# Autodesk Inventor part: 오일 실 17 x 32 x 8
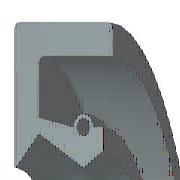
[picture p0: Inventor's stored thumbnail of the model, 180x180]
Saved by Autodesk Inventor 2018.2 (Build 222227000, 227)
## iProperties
Created: 2012-02
Part Number: 오일 실 17 x 32 x 8
Material: 고무
Description: 샤프트 실 링
Document SubType Name: Modeling
Standard: JIS B 2402
Designer: mdu-01
Standards Organization: JIS
Language: ko-KR
Size Designation: D 17 x 32 x 8
Categories: <MemberInstance><Categories><Category DisplayName="샤프트 부품" InternalName="7f7aeb1f-a693-4053-b835-cee3144e0d98" Mnemonic="SHFT"><Category DisplayName="실링" Intern
Density: 0.93 g/cm^3
Mass: 2.28027 g
Surface Area: 32.1224 cm^2
Volume: 2.45191 cm^3
Appearance: 고무 - 검은색 - 버전 1.1
IsCustomPart: 1
Author: mdu-01
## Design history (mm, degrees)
revolve "본체" stored, may be unused: angle "d17" = 90 deg
revolve "스프링1" stored, may be unused: angle "d18" = 90 deg
body "Solid1"
sketch "스케치1"
  geometry: L1 (0, 16)-(8, 16); L2 (8, 14.25)-(1.75, 14.25); L3 (1.75, 10.25)-(4.9, 8.5); L4 (4.9, 8.5)-(0, 8.5); L5 (0, 0)-(9.586, 0) reference; L6 (4.9, 8.5)-(6.3, 9.375); L7 (0, 18)-(0, -3) reference; L8 (-1.941, 0)-(11.507, 0) reference; L9 (4.2, 10.6)-(1.75, 11.21); L10 (1.75, 11.21)-(1.75, 14.25); L11 (0, 16)-(0, 8.588); L12 (4.9, 8.5)-(0, 8.5); L13 (1.75, 10.25)-(0.152, 8.528); L14 (8, 16)-(8, 14.25); L15 (5.6, 10.6)-(6.3, 10.6); L16 (6.3, 10.6)-(6.3, 9.375); C1 r 0.455 at (4.9, 10.6); A1 r 0.7 centre (4.9, 10.6) between (5.6, 10.6) and (4.2, 10.6); A2 r 0.088 centre (0.088, 8.588) between (0, 8.588) and (0.152, 8.528); 1 further point
  constraints: 28 end point, 5 horizontal alignment, 5 point on line, 4 point on circle, 4 vertical alignment, 3 centre point, 3 tangent, 2 collinear, 2 horizontal, 2 perpendicular, 1 coincident, 1 parallel
  dimensions: "d0" = 32 diameter of L1 L5 (= SD2); "d1" = 1.75 distance of L1.end L2.start (= SD); "d2" = 0.91 diameter of C1 (= SPDI); "d3" = 1.4 diameter of A1 (= SPDA); "d4" = 17 diameter of L3.end L5 (= NND); "d5" = 20.5 diameter of L3.start L5 (= TKDM); "d7" = 22.42 diameter of L9.end L5 (= TKDM + 0.24 x SWDT); "d8" = 1.75 distance between parallel lines of L11 L10 (= SD); "d9" = 4.9 distance from line of L11 C1.centre (= SPDST); "d10" = 21.2 diameter of C1.centre L5 (= HLDM); "d11" = 0.0875 radius of A2 (= 0.25 x LAB); "d12" = 6.3 distance between parallel lines of L11 L16 (= SDI); "d13" = 18.75 diameter of L6.end L5 (= ABDM); "d14" = 8 distance from line of L11 L1.end (= SWDT)
fillet "모깎기1" dims "d6" = 0.3 (= RR)
other parameters: "SD2" = 32 [user parameter; used in 1 equation term], "SWDT" = 8 [user parameter; used in 2 equation terms], "RR" = 0.3 [user parameter; used in 1 equation term], "SD" = 1.75 [user parameter; used in 2 equation terms], "NND" = 17 [user parameter; used in 1 equation term], "SPDA" = 1.4 [user parameter; used in 1 equation term], "SPDI" = 0.91 [user parameter; used in 1 equation term], "TKDM" = 20.5 [user parameter; used in 2 equation terms], "HLDM" = 21.2 [user parameter; used in 1 equation term], "ABDM" = 18.75 [user parameter; used in 1 equation term], "SDI" = 6.3 [user parameter; used in 1 equation term], "SPDST" = 4.9 [user parameter; used in 1 equation term], "LAB" = 0.35 [user parameter; used in 1 equation term], "d15" = 0, "d16" = 0, "d19" = 0
